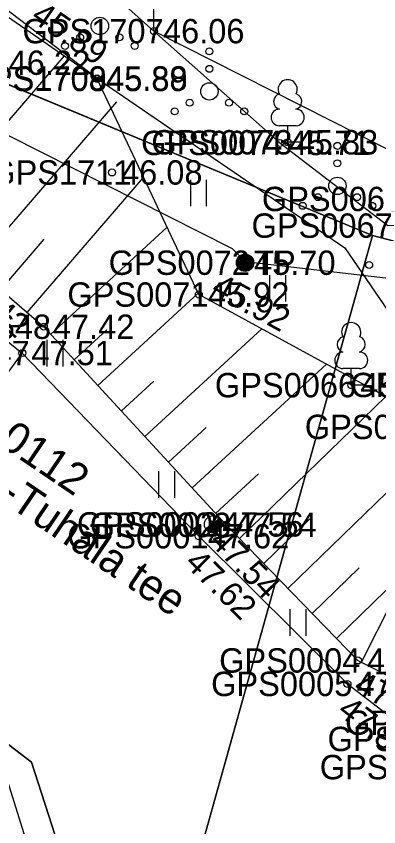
# Model space of a CAD drawing. Extents: x 551623 to 559850, y 6561220 to 6567135.
# Drawn here: x 555053.18 to 555063.61, y 6565630.28 to 6565653.59 of the extents above; entities that cross this region are included whole.
import ezdxf

# ---------------------------------------------------------------- set-up
doc = ezdxf.new("R2010")
doc.units = 0
for name, color, linetype in [('AED', 7, 'Continuous'), ('HALJASTUS', 7, 'Continuous'), ('Hoone Vare', 7, 'Continuous'), ('KORGUS-EH2000', 7, 'Continuous'), ('MOOTKORG-EH2000', 7, 'Continuous'), ('MOOTMPUNKT', 7, 'Continuous'), ('MOOTNR', 7, 'Continuous'), ('MOOTPIIR', 7, 'Continuous'), ('MPKAABEL', 7, 'Continuous'), ('PIIR', 7, 'Continuous'), ('POST', 7, 'Continuous'), ('PUU', 7, 'Continuous'), ('RELJEEF', 7, 'Continuous'), ('TEE', 7, 'Continuous')]:
    doc.layers.add(name, color=color, linetype=linetype)

msp = doc.modelspace()

# ---------------------------------------------------------------- linework, layer by layer
at = {"layer": 'AED'}
for points in [[(555057.142, 6565653.162), (555050.543, 6565659.052), (555042.979, 6565665.343), (555043.174, 6565665.907), (555043.846, 6565668.219)], [(555057.142, 6565653.162), (555060.763, 6565649.947), (555063.868, 6565647.57), (555078.093, 6565647.789), (555094.907, 6565648.285)]]:
    msp.add_lwpolyline(points, dxfattribs=at)
at = {"layer": 'HALJASTUS'}
for p, q in [((555058.189, 6565648.887), (555058.189, 6565648.125)), ((555058.644, 6565648.887), (555058.644, 6565648.125)), ((555060.467, 6565646.148), (555060.467, 6565645.387)), ((555060.922, 6565646.148), (555060.922, 6565645.387)), ((555054.066, 6565644.282), (555054.066, 6565643.521)), ((555054.521, 6565644.282), (555054.521, 6565643.521)), ((555057.275, 6565640.504), (555057.275, 6565639.743)), ((555057.73, 6565640.504), (555057.73, 6565639.743)), ((555061.05, 6565636.538), (555061.05, 6565635.776)), ((555061.505, 6565636.538), (555061.505, 6565635.776))]:
    msp.add_line(p, q, dxfattribs=at)
for points in [[(555055.505, 6565651.803), (555048.596, 6565657.055), (555041.121, 6565664.646), (555033.726, 6565668.167), (555033.718, 6565670.144), (555033.986, 6565673.185)], [(555055.505, 6565651.803), (555062.627, 6565646.926), (555070.89, 6565634.851), (555085.128, 6565639.729), (555086.548, 6565638.793), (555087.649, 6565638.791), (555086.883, 6565641.904), (555087.023, 6565643.49), (555093.202, 6565645.67), (555094.219, 6565648.275)]]:
    msp.add_lwpolyline(points, dxfattribs=at)
for centre, radius in [((555055.586, 6565653.311), 0.25), ((555055.021, 6565652.986), 0.1), ((555056.151, 6565652.986), 0.1), ((555054.586, 6565652.736), 0.1), ((555056.586, 6565652.736), 0.1), ((555058.737, 6565652.578), 0.1), ((555058.737, 6565652.078), 0.1), ((555058.737, 6565651.428), 0.25), ((555058.172, 6565651.103), 0.1), ((555059.302, 6565651.103), 0.1), ((555057.737, 6565650.853), 0.1), ((555059.737, 6565650.853), 0.1), ((555062.418, 6565649.863), 0.1), ((555062.418, 6565649.363), 0.1), ((555062.418, 6565648.713), 0.25), ((555061.853, 6565648.388), 0.1), ((555062.983, 6565648.388), 0.1), ((555061.418, 6565648.138), 0.1), ((555063.418, 6565648.138), 0.1), ((555063.33, 6565646.438), 0.1)]:
    msp.add_circle(centre, radius, dxfattribs=at)
at = {"layer": 'Hoone Vare'}
msp.add_lwpolyline([(555056.391, 6565620.508), (555048.876, 6565618.166), (555045.371, 6565629.41), (555052.886, 6565631.752)], close=True, dxfattribs=at)
at = {"layer": 'KORGUS-EH2000'}
for centre in [(555057.142, 6565653.162), (555055.505, 6565651.803), (555060.763, 6565649.947), (555055.936, 6565649.098), (555058.433, 6565645.588), (555053.976, 6565644.662), (555053.358, 6565643.906), (555062.814, 6565642.982), (555059.218, 6565638.966), (555058.43, 6565638.637), (555063.006, 6565635.065), (555062.706, 6565634.391)]:
    msp.add_circle(centre, 0.1, dxfattribs=at)
at = {"layer": 'MOOTMPUNKT'}
for centre in [(555057.142, 6565653.162), (555055.505, 6565651.803), (555055.507, 6565651.786), (555060.763, 6565649.947), (555060.987, 6565649.967), (555055.936, 6565649.098), (555059.761, 6565646.503), (555058.433, 6565645.588), (555053.976, 6565644.662), (555053.358, 6565643.906), (555062.814, 6565642.982), (555058.845, 6565638.979), (555059.218, 6565638.966), (555058.43, 6565638.637), (555063.006, 6565635.065), (555062.706, 6565634.391)]:
    msp.add_circle(centre, 0.1, dxfattribs=at)
at = {"layer": 'MOOTPIIR'}
msp.add_lwpolyline([(555050.244, 6565639.614), (555053.358, 6565643.906), (555058.43, 6565638.637), (555062.706, 6565634.391), (555065.829, 6565631.998), (555069.987, 6565631.13), (555073.594, 6565631.301), (555077.505, 6565632.778), (555089.342, 6565637.222), (555090.377, 6565638.461), (555094.165, 6565645.802), (555095.317, 6565648.328), (555095.66, 6565648.918), (555092.332, 6565650.666), (555085.208, 6565648.465), (555080.589, 6565649.38), (555070.954, 6565650.337), (555063.92, 6565649.728), (555057.142, 6565653.162), (555057.121, 6565656.605), (555043.846, 6565668.219)], dxfattribs=at)
at = {"layer": 'MPKAABEL'}
msp.add_lwpolyline([(555016.481, 6565670.066), (555020.706, 6565667.922), (555024.517, 6565664.875), (555027.056, 6565662.52), (555029.673, 6565661.024), (555034.413, 6565659.21), (555039.915, 6565656.802), (555046.244, 6565654.185), (555052.975, 6565650.153), (555059.391, 6565646.912), (555059.766, 6565646.536), (555063.804, 6565646.065), (555068.88, 6565645.207), (555082.81, 6565641.043), (555083.734, 6565640.909), (555084.772, 6565641.269), (555085.39, 6565641.873), (555087.19, 6565643.44), (555089.359, 6565644.841), (555090.654, 6565645.869), (555090.907, 6565646.435), (555093.14, 6565648.67), (555093.546, 6565648.774)], dxfattribs=at)
at = {"layer": 'PIIR'}
for points in [[(554603.79, 6565845.49), (554627.12, 6565842.3), (554665.57, 6565833.57), (554691.68, 6565822.99), (554755.19, 6565793.15), (554758.98, 6565791.67), (554762.76, 6565790.19), (554847.58, 6565749.85), (555047.17, 6565654.02), (555063.43, 6565647.29), (555056.61, 6565622.91), (555053.62, 6565632.14), (555043.11, 6565640.11), (555030.24, 6565648.23), (554842.52, 6565736.67), (554759.53, 6565776.27), (554755.81, 6565778.04), (554752.09, 6565779.79), (554661.37, 6565820.17), (554624.59, 6565828.52)], [(555147.74, 6565789.33), (555183.27, 6565722.97), (555183.08, 6565715.21), (555166.23, 6565703.46), (555159.38, 6565687.44), (555141.63, 6565659.29), (555137.2, 6565645.72), (555136.5, 6565633.07), (555130.73, 6565621.32), (555129.77, 6565611.2), (555114.24, 6565634), (555063.43, 6565647.29), (555047.17, 6565654.02), (554847.58, 6565749.85)], [(554759.9, 6565289.12), (554708.97, 6565534.83), (554708.61, 6565545.48), (554711.27, 6565557.85), (554755.81, 6565778.04), (554759.53, 6565776.27), (554842.52, 6565736.67), (555030.24, 6565648.23), (555043.11, 6565640.11), (555053.62, 6565632.14), (555056.61, 6565622.91), (555057.22, 6565600.73), (555060.42, 6565583.26), (555065.78, 6565566.7), (555076.76, 6565542.38), (555113.82, 6565475.68), (554946.63, 6565420.78), (554981.01, 6565316.76), (555160.07, 6565375.54), (555166.64, 6565360.5), (555172.72, 6565345.23)], [(555172.72, 6565345.23), (555166.64, 6565360.5), (555160.07, 6565375.54), (555144.16, 6565410.6), (555124.27, 6565454.45), (555113.82, 6565475.68), (555076.76, 6565542.38), (555065.78, 6565566.7), (555060.42, 6565583.26), (555057.22, 6565600.73), (555056.61, 6565622.91), (555063.43, 6565647.29), (555114.24, 6565634), (555129.77, 6565611.2), (555130.73, 6565621.32), (555138.66, 6565615.26), (555160.12, 6565598.86), (555193.24, 6565604.68)]]:
    msp.add_lwpolyline(points, dxfattribs=at)
at = {"layer": 'POST'}
msp.add_line((555058.667, 6565638.803), (555059.021, 6565639.156), dxfattribs=at)
for centre, radius in [((555059.761, 6565646.503), 0.25), ((555059.761, 6565646.503), 0.225), ((555059.761, 6565646.503), 0.2), ((555059.761, 6565646.503), 0.175), ((555059.761, 6565646.503), 0.15), ((555059.761, 6565646.503), 0.125), ((555059.761, 6565646.503), 0.1), ((555059.761, 6565646.503), 0.075), ((555059.761, 6565646.503), 0.05), ((555059.761, 6565646.503), 0.025), ((555058.845, 6565638.979), 0.25)]:
    msp.add_circle(centre, radius, dxfattribs=at)
for radius, start, end in [(0.225, 224.8541, 45.0356), (0.2, 224.8427, 45.047), (0.175, 224.8281, 45.0616), (0.15, 224.8087, 45.081), (0.125, 224.7814, 45.1083), (0.1, 224.7406, 45.1491), (0.075, 224.6725, 45.2172), (0.05, 224.5363, 45.3534), (0.025, 224.1278, 45.7619)]:
    msp.add_arc((555058.845, 6565638.979), radius, start, end, dxfattribs=at)
at = {"layer": 'PUU'}
for p, q in [((555061.227, 6565650.442), (555060.747, 6565650.442)), ((555060.987, 6565649.967), (555060.987, 6565650.442)), ((555061.367, 6565649.967), (555060.987, 6565649.967)), ((555063.054, 6565643.457), (555062.574, 6565643.457)), ((555062.814, 6565642.982), (555062.814, 6565643.457)), ((555063.194, 6565642.982), (555062.814, 6565642.982))]:
    msp.add_line(p, q, dxfattribs=at)
for centre, radius, start, end in [((555060.987, 6565651.487), 0.277, 332.5799, 207.4201), ((555060.817, 6565651.14), 0.233, 109.0217, 253.1415), ((555061.157, 6565651.14), 0.233, 286.8508, 70.9859), ((555060.749, 6565650.679), 0.238, 90.0016, 269.3953), ((555061.224, 6565650.679), 0.238, 270.6047, 89.9984), ((555062.814, 6565644.502), 0.277, 332.5799, 207.4201), ((555062.644, 6565644.155), 0.233, 109.0217, 253.1415), ((555062.984, 6565644.155), 0.233, 286.8508, 70.9859), ((555062.577, 6565643.695), 0.238, 90.0016, 269.3953), ((555063.052, 6565643.695), 0.238, 270.6047, 89.9984)]:
    msp.add_arc(centre, radius, start, end, dxfattribs=at)
at = {"layer": 'RELJEEF'}
for p, q in [((555050.468, 6565647.685), (555054.564, 6565652.439)), ((555051.983, 6565646.379), (555056.079, 6565651.133)), ((555053.498, 6565645.074), (555056.843, 6565648.956)), ((555054.174, 6565644.446), (555057.519, 6565647.524)), ((555052.741, 6565645.727), (555053.99, 6565647.177)), ((555055.529, 6565642.975), (555058.414, 6565645.63)), ((555054.852, 6565643.71), (555055.786, 6565644.57)), ((555056.883, 6565641.503), (555060.246, 6565644.598)), ((555058.238, 6565640.031), (555062.099, 6565643.585)), ((555056.206, 6565642.239), (555057.14, 6565643.098)), ((555059.603, 6565638.57), (555063.806, 6565642.652)), ((555057.56, 6565640.767), (555058.644, 6565641.764)), ((555060.996, 6565637.135), (555065.564, 6565641.571)), ((555058.915, 6565639.296), (555060.148, 6565640.43)), ((555062.389, 6565635.7), (555066.806, 6565639.99)), ((555060.299, 6565637.853), (555061.627, 6565639.142)), ((555061.693, 6565636.418), (555063.04, 6565637.727)), ((555063.109, 6565635.014), (555064, 6565636.784))]:
    msp.add_line(p, q, dxfattribs=at)
for points in [[(555033.894, 6565670.212), (555034.614, 6565663.057), (555035.301, 6565660.376), (555036.779, 6565657.701), (555046.65, 6565650.974), (555053.976, 6565644.662), (555059.218, 6565638.966), (555063.006, 6565635.065), (555066.558, 6565633.276), (555069.932, 6565631.832), (555073.49, 6565632.167), (555077.147, 6565633.608), (555087.05, 6565637.366), (555088.79, 6565638.512), (555093.706, 6565645.854), (555094.519, 6565648.167)], [(555094.519, 6565648.167), (555091.768, 6565644.364), (555088.888, 6565641.514), (555084.532, 6565638.225), (555081.733, 6565636.397), (555078.271, 6565636.1), (555072.848, 6565637.573), (555070.427, 6565635.378), (555065.399, 6565641.782), (555058.433, 6565645.588), (555055.507, 6565651.786), (555048.138, 6565656.889), (555042.979, 6565656.577), (555037.014, 6565660.866), (555035.735, 6565662.759), (555033.894, 6565670.212)]]:
    msp.add_lwpolyline(points, dxfattribs=at)
at = {"layer": 'TEE'}
msp.add_lwpolyline([(555020.473, 6565663.799), (555033.164, 6565657.977), (555034.731, 6565658.02), (555036.161, 6565657.119), (555036.314, 6565656.164), (555045.718, 6565650.093), (555053.358, 6565643.906), (555058.43, 6565638.637), (555062.706, 6565634.391), (555065.829, 6565631.998), (555069.987, 6565631.13), (555073.594, 6565631.301), (555077.505, 6565632.778), (555087.215, 6565636.533), (555089.342, 6565637.222), (555090.377, 6565638.461), (555094.165, 6565645.802), (555095.317, 6565648.328), (555095.882, 6565650.082)], dxfattribs=at)

# ---------------------------------------------------------------- texts
at = {"layer": 'KORGUS-EH2000'}
for s, rotation, p in [(' 45.89', 325.3, (555053.354, 6565653.631)), (' 47.42', 319.249, (555051.212, 6565645.999)), (' 45.92', 331.3455, (555058.517, 6565645.742)), (' 47.54', 314.1618, (555058.521, 6565638.642)), (' 47.62', 315.2064, (555057.813, 6565638.016)), (' 47.80', 333.2661, (555062.613, 6565634.284)), (' 47.86', 322.5365, (555062.174, 6565633.697))]:
    msp.add_text(s, height=0.7, rotation=rotation, dxfattribs=at).set_placement(p)
for s, p in [(' 46.06', (555057.142, 6565652.812)), (' 45.71', (555060.763, 6565649.597)), (' 46.08', (555055.936, 6565648.748)), (' 45.97', (555062.814, 6565642.632))]:
    msp.add_text(s, height=0.7, dxfattribs=at).set_placement(p)
at = {"layer": 'MOOTKORG-EH2000'}
for s, p in [(' 46.06', (555057.142, 6565652.812)), (' 46.22', (555052.705, 6565651.904)), (' 45.88', (555055.505, 6565651.453)), (' 45.89', (555055.507, 6565651.436)), (' 45.71', (555060.763, 6565649.597)), (' 45.83', (555060.987, 6565649.617)), (' 46.08', (555055.936, 6565648.748)), (' 45.70', (555059.761, 6565646.153)), (' 45.92', (555058.433, 6565645.238)), (' 47.42', (555053.976, 6565644.312)), (' 47.51', (555053.358, 6565643.556)), (' 45.97', (555062.814, 6565642.632)), (' 47.56', (555058.845, 6565638.629)), (' 47.54', (555059.218, 6565638.616)), (' 47.62', (555058.43, 6565638.287)), (' 47.80', (555063.006, 6565634.715)), (' 47.86', (555062.706, 6565634.041))]:
    msp.add_text(s, height=0.7, dxfattribs=at).set_placement(p)
at = {"layer": 'MOOTNR'}
for s, p in [('GPS1707 ', (555053.362, 6565652.812)), ('GPS1709 ', (555051.725, 6565651.453)), ('GPS1708 ', (555051.727, 6565651.436)), ('GPS0074 ', (555056.773, 6565649.597)), ('GPS0073 ', (555057.067, 6565649.617)), ('GPS1711 ', (555052.436, 6565648.748)), ('GPS0068 ', (555060.246, 6565647.986)), ('GPS0067 ', (555059.948, 6565647.22)), ('GPS0072 ', (555055.841, 6565646.153)), ('GPS0071 ', (555054.653, 6565645.238)), ('GPS1648 ', (555050.126, 6565644.312)), ('GPS1647 ', (555049.509, 6565643.556)), ('GPS0066 ', (555058.895, 6565642.632)), ('GPS0064 ', (555062.788, 6565642.637)), ('GPS0065 ', (555061.479, 6565641.432)), ('GPS0002 ', (555054.925, 6565638.629)), ('GPS0003 ', (555055.298, 6565638.616)), ('GPS0001 ', (555054.65, 6565638.287)), ('GPS0004 ', (555059.016, 6565634.715)), ('GPS0005 ', (555058.786, 6565634.041)), ('GPS0008 ', (555062.638, 6565632.926)), ('GPS0007 ', (555062.133, 6565632.458)), ('GPS0006 ', (555061.909, 6565631.648))]:
    msp.add_text(s, height=0.7, dxfattribs=at).set_placement(p)
at = {"layer": 'PIIR'}
for s, p in [('33701:001:0112', (555047.668, 6565644.65)), ('11115 Kurna-Tuhala tee', (555046.938, 6565643.574))]:
    msp.add_text(s, height=0.9, rotation=325.8834, dxfattribs=at).set_placement(p)
at = {"layer": 'POST'}
msp.add_text(' TP', height=0.7, dxfattribs=at).set_placement((555059.761, 6565646.153))

doc.saveas('drawing.dxf')
